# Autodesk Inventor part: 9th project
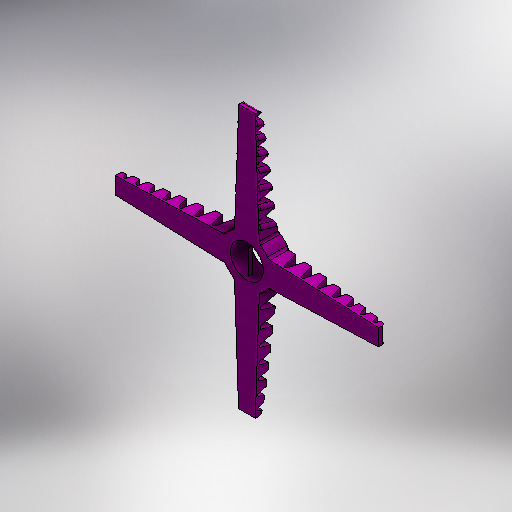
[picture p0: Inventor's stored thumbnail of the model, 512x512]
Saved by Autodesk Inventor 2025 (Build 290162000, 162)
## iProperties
Created: 2018-03
Part Number: 9th project
Material: Rubber, Silicone
Document SubType Name: Modeling
Designer: PSP
Density: 1.25 g/cm^3
Appearance: Semi-Polished
Author: PSP
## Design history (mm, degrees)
sketch "Sketch1"
  geometry: C1 r 15 at (0, 0); 1 further point
  constraints: 1 centre point, 1 coincident
  dimensions: "d0" = 30 diameter of C1
extrude "Extrusion1" new body sketch "Sketch1" distance "d1" = 15; taper "d2" = 0 deg
sketch "Sketch5"
  geometry: L1 (0, 15)-(0, -15) reference; L2 (0, 15)-(15, 15) reference; L3 (0, 0)-(19.654, 0); L4 (0, 5)-(14, 5); L5 (14, 5)-(14, 18.5); L6 (14, 18.5)-(4, 21.179); L7 (0, 80)-(0, 0); L8 (4, 80)-(-4.229, 80); L9 (4, 21.179)-(4, 22.679); L10 (4, 22.679)-(13, 25.091); L11 (13, 25.091)-(13, 29.091); L12 (13, 29.091)-(4, 31.503); L13 (4, 31.503)-(4, 33.003); L14 (4, 33.003)-(12, 35.146); L15 (12, 35.146)-(12, 39.146); L16 (12, 39.146)-(4, 41.29); L17 (4, 41.29)-(4, 42.79); L18 (4, 42.79)-(11, 44.665); L19 (11, 44.665)-(11, 48.665); L20 (11, 48.665)-(4, 50.541); L21 (4, 52.041)-(10, 53.649); L22 (10, 53.649)-(10, 57.649); L23 (10, 57.649)-(4, 59.256); L24 (4, 50.541)-(4, 52.041); L25 (4, 59.256)-(4, 60.756); L26 (4, 60.756)-(9, 62.096); L27 (9, 62.096)-(9, 66.096); L28 (9, 66.096)-(4, 67.436); L29 (4, 67.436)-(4, 68.936); L30 (4, 68.936)-(8, 70.008); L31 (8, 70.008)-(8, 74.008); L32 (8, 74.008)-(4, 75.08); L33 (4, 75.08)-(4, 76.58); L34 (4, 76.58)-(7, 77.383); L35 (7, 77.383)-(7, 80); L36 (7, 80)-(4, 80); 1 further point
  constraints: 68 end point, 6 parallel, 5 point on line, 4 horizontal, 3 vertical, 2 perpendicular, 1 collinear, 16 other
  dimensions: "d23" = 10 diameter of L4 L3; "d24" = 13.5 distance of L4.end L5.end; "d25" = 105 deg angle of L6 L5; "d45" = 4 dimension on L1; "d46" = 1.5 distance of L6.end L9.end; "d47" = 105 deg angle of L9 L10; "d48" = 4 distance of L10.end L11.end; "d49" = 1.5 distance of L12.end L13.end; "d50" = 105 deg angle of L13 L14; "d51" = 4 distance of L14.end L15.end; "d52" = 1.5 distance of L16.end L17.end; "d58" = 75 deg angle to the sketch y axis of L12; "d61" = 8 dimension on L15; "d63" = 9 dimension on L11; "d64" = 4 distance of L18.end L19.end; "d65" = 7 dimension on L19; "d66" = 105 deg dimension on L18; "d67" = 105 deg dimension on L20; "d68" = 4 distance of L21.end L22.end; "d69" = 1.5 distance of L20.end L21.start; "d70" = 6 dimension on L22; "d71" = 105 deg dimension on L23; "d72" = 75 deg angle to the sketch y axis of L21; "d73" = 1.5 distance of L23.end L25.end; "d74" = 105 deg angle of L25 L26; "d75" = 4 distance of L26.end L27.end; "d76" = 5 dimension on L27; "d77" = 1.5 distance of L28.end L29.end; "d78" = 105 deg angle of L29 L30; "d79" = 4 distance of L30.end L31.end; "d80" = 105 deg angle of L32 L31; "d81" = 1.5 distance of L32.end L33.end; "d82" = 105 deg angle of L35 L34; "d83" = 4 length of L31
extrude "Extrusion2" join sketch "Sketch5" stored distance "d84" = 15; taper "d85" = 0 deg
fillet "Fillet1" dims "d86" = 2
fillet "Fillet2" dims "d87" = 1
fillet "Fillet4" dims "d89" = 1
fillet "Fillet5" dims "d90" = 1
fillet "Fillet6" dims "d91" = 1
fillet "Fillet7" dims "d92" = 1
fillet "Fillet8" dims "d93" = 1
fillet "Fillet9" dims "d94" = 1
fillet "Fillet10" dims "d95" = 1
fillet "Fillet11" dims "d96" = 1
fillet "Fillet12" dims "d97" = 1
fillet "Fillet13" dims "d98" = 1
fillet "Fillet14" dims "d99" = 1
fillet "Fillet15" dims "d100" = 1
fillet "Fillet16" dims "d101" = 1
sketch "Sketch9"
  geometry: L1 (-7.5, 12.99)-(-7.5, 79); L2 (-7.5, 78)-(-7.5, 80) reference; L3 (7.5, 12.99)-(7.5, 79); L4 (7.5, 80)-(7.5, 12.99) reference; L5 (7.5, 78)-(7.5, 82.569); L6 (7.5, 82.569)-(5, 82.569); L7 (5, 82.569)-(5, 82.569); L8 (-7.5, 80)-(7.5, 80) reference; L9 (-7.5, 79)-(-7.5, 82.571); L10 (-7.5, 82.571)-(-5, 82.571); L11 (5, 82.569)-(7.5, 12.99); L12 (-5, 82.571)-(-7.5, 12.99); 1 further point
  constraints: 18 end point, 2 collinear, 2 perpendicular, 2 vertical, 1 horizontal
  dimensions: "d107" = 2.5 distance of L5.end L6.end; "d108" = 2.5 distance of L9.end L10.end
extrude "Extrusion3" cut sketch "Sketch9" extent not by distance; stored distance "d109" = 0; taper "d110" = 0 deg
fillet "Fillet17" dims "d111" = 2
fillet "Fillet18" dims "d112" = 2
fillet "Fillet19" dims "d113" = 1
pattern_circular "Circular Pattern1" dims angle "d115" = 360 deg
fillet "Fillet20" dims "d117" = 1
fillet "Fillet21" dims "d118" = 1
fillet "Fillet22" dims "d119" = 1
fillet "Fillet23" dims "d120" = 2
fillet "Fillet24" dims "d121" = 2
fillet "Fillet25" dims "d122" = 2
fillet "Fillet26" dims "d123" = 2
fillet "Fillet27" dims "d124" = 2
fillet "Fillet28" dims "d125" = 2
sketch "Sketch11"
  geometry: L1 (-7.5, -14.133)-(-7.5, -80); L2 (-7.5, -80)-(-7.5, -82.569); L3 (-7.5, -82.569)-(-5, -82.569); L4 (-5, -82.569)-(-7.5, -14.133); L5 (7.5, -14.133)-(7.5, -80); L6 (5, -82.569)-(7.5, -14.133); L7 (7.5, -80)-(7.5, -82.569); L8 (7.5, -82.569)-(5, -82.569); 1 further point
  constraints: 16 end point, 2 point on line, 1 perpendicular, 1 vertical
  dimensions: "d126" = 2.569 distance of L1.end L2.end; "d127" = 2.5 distance of L2.end L3.end
extrude "Extrusion4" cut sketch "Sketch11" extent not by distance; stored distance "d128" = 0; taper "d129" = 0 deg
sketch "Sketch12"
  geometry: L1 (14.098, -7.5)-(80, -7.5); L2 (80, -7.5)-(82.569, -7.5); L3 (82.569, -7.5)-(82.569, -5); L4 (82.569, -5)-(14.098, -7.5); L5 (14.098, 7.5)-(80, 7.5); L6 (80, 7.5)-(82.569, 7.5); L7 (82.569, 7.5)-(82.569, 5); L8 (82.569, 5)-(14.098, 7.5); A1 r 16 centre (0, 0) between (14.133, -7.5) and (14.133, 7.5) reference; 1 further point
  constraints: 16 end point, 2 point on line, 1 horizontal, 1 perpendicular
  dimensions: "d130" = 2.569 distance of L1.end L2.end; "d131" = 2.5 distance of L2.end L3.end
extrude "Extrusion5" cut sketch "Sketch12" extent not by distance; stored distance "d132" = 0; taper "d133" = 0 deg
sketch "Sketch13"
  geometry: L1 (-14.281, 7.5)-(-80, 7.5); L2 (-80, 7.5)-(-82.569, 7.5); L3 (-82.569, 7.5)-(-82.569, 5); L4 (-14.281, 7.5)-(-82.569, 5); L5 (-14.281, -7.5)-(-80, -7.5); L6 (-14.281, -7.5)-(-82.569, -5); L7 (-82.569, -7.5)-(-82.569, -5); L8 (-80, -7.5)-(-82.569, -7.5); 1 further point
  constraints: 16 end point, 2 point on line, 1 horizontal, 1 perpendicular
  dimensions: "d134" = 2.569 distance of L1.end L2.end; "d135" = 2.5 distance of L2.end L3.end
extrude "Extrusion6" cut sketch "Sketch13" extent not by distance; stored distance "d136" = 0; taper "d137" = 0 deg
sketch "Sketch14"
  geometry: C1 r 10 at (0, 0); 1 further point
  constraints: 1 centre point, 1 coincident
  dimensions: "d138" = 20 diameter of C1
extrude "Extrusion7" cut sketch "Sketch14" extent not by distance; stored distance "d139" = 10; taper "d140" = 0 deg
fillet "Fillet29" dims "d141" = 2
fillet "Fillet30" dims "d142" = 2
fillet "Fillet31" dims "d143" = 2
sketch "Sketch16"
  geometry: L1 (0, -5.094)-(0, 5.094) reference; L2 (5.5, 7.5)-(0, 7.5); L3 (0, 7.5)-(0, -7.5); L4 (0, -7.5)-(5.5, -7.5); L5 (5.5, -7.5)-(5.5, 7.5); 1 further point
  constraints: 8 end point, 2 parallel, 1 horizontal, 1 perpendicular, 1 point on line
  dimensions: "d144" = 15 distance of L4.end L2.start; "d145" = 7.5 distance from line of point (0, 0) L2; "d146" = 5.5 distance of L3.end L4.end
extrude "Extrusion8" join sketch "Sketch16" distance "d147" = 1; taper "d148" = 0 deg
fillet "Fillet32" dims "d149" = 1
fillet "Fillet33" dims "d150" = 1
fillet "Fillet34" dims "d151" = 1
fillet "Fillet35" dims "d152" = 1
fillet "Fillet36" dims "d153" = 1
fillet "Fillet37" dims "d154" = 1
fillet "Fillet38" dims "d155" = 1
fillet "Fillet39" dims "d156" = 1
fillet "Fillet40" dims "d157" = 1
fillet "Fillet41" dims "d158" = 1
fillet "Fillet42" dims "d159" = 1
fillet "Fillet43" dims "d160" = 1
fillet "Fillet44" dims "d161" = 1
fillet "Fillet45" dims "d162" = 1
fillet "Fillet46" dims "d163" = 1
fillet "Fillet47" dims "d164" = 1
fillet "Fillet48" dims "d165" = 1
fillet "Fillet49" dims "d166" = 1
fillet "Fillet50" dims "d167" = 1
fillet "Fillet51" dims "d168" = 1
fillet "Fillet52" dims "d169" = 1
fillet "Fillet53" dims "d170" = 1
fillet "Fillet54" dims "d171" = 1
fillet "Fillet55" dims "d172" = 1
fillet "Fillet56" dims "d173" = 1
fillet "Fillet57" dims "d174" = 1
fillet "Fillet58" dims "d175" = 1
fillet "Fillet59" dims "d176" = 1
fillet "Fillet60" dims "d177" = 1
fillet "Fillet61" dims "d178" = 1
fillet "Fillet62" dims "d179" = 1
fillet "Fillet63" dims "d180" = 1
fillet "Fillet64" dims "d181" = 1
fillet "Fillet65" dims "d182" = 1
fillet "Fillet66" dims "d183" = 1
fillet "Fillet67" dims "d184" = 1
fillet "Fillet68" dims "d185" = 1
fillet "Fillet69" dims "d186" = 1
fillet "Fillet70" dims "d187" = 1
fillet "Fillet71" dims "d188" = 1
fillet "Fillet72" dims "d189" = 1
fillet "Fillet73" dims "d190" = 1
fillet "Fillet74" dims "d191" = 1
fillet "Fillet75" dims "d192" = 1
sketch "Sketch18"
  geometry: L1 (-151.155, 3)-(154.345, 3); L2 (154.345, 3)-(154.345, 0); L3 (154.345, 0)-(-151.155, 0); L4 (-151.155, 0)-(-151.155, 3); 1 further point
  constraints: 8 end point, 2 parallel, 1 horizontal, 1 perpendicular
  dimensions: "d193" = 3 distance of L3.end L1.start
extrude "Extrusion9" cut sketch "Sketch18" extent not by distance; stored distance "d194" = 7.5; taper "d195" = 0 deg
fillet "Fillet76" dims "d196" = 2
fillet "Fillet77" dims "d197" = 2
fillet "Fillet78" dims "d198" = 2
fillet "Fillet79" dims "d199" = 2
fillet "Fillet80" dims "d200" = 2
fillet "Fillet81" dims "d201" = 2
feature "ખ耀ઘ耀ચ耀જ耀ઞ耀ઠ耀ઢ耀ત耀" dims "d0" = 30, "d1" = 15, "d2" = 0, "d23" = 10, "d24" = 13.5, "d25" = 105 deg, "d45" = 4, "d46" = 1.5, "d47" = 105 deg, "d48" = 4, "d49" = 1.5, "d50" = 105 deg, "d51" = 4, "d52" = 1.5, "d58" = 75 deg, "d61" = 8, "d63" = 9, "d64" = 4, "d65" = 7, "d66" = 105 deg, "d67" = 105 deg, "d68" = 4, "d69" = 1.5, "d70" = 6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
body "Solid1"
sketch "Sketch17"
  geometry: 1 further point
